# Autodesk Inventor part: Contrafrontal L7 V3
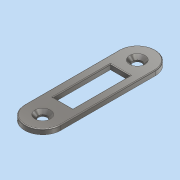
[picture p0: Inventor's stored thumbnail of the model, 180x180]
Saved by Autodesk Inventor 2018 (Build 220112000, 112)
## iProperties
Created: 2020-04
Part Number: Contrafrontal L7 V3
Material: Acero inoxidable
Document SubType Name: Modeling
Designer: PROYECTO
Density: 8 g/cm^3
Appearance: Semipulido
Author: PROYECTO
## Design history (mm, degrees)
sketch "Boceto1"
  geometry: L1 (0, 0)-(0, 80); L2 (11, 11)-(11, 69); L3 (-11, 69)-(-11, 11); L4 (6, 23.5)-(-6, 23.5); L5 (-6, 23.5)-(-6, 58.5); L6 (-6, 58.5)-(6, 58.5); L7 (6, 58.5)-(6, 23.5); L8 (6, 23.5)-(-6, 58.5); L9 (-6, 23.5)-(6, 58.5); C1 r 2.75 at (0, 69); C2 r 2.75 at (0, 11); A1 r 11 centre (0, 11) between (-11, 11) and (11, 11); A2 r 11 centre (0, 69) between (11, 69) and (-11, 69); 2 further points
  constraints: 20 end point, 6 point on circle, 4 centre point, 4 tangent, 3 midpoint, 3 parallel, 3 point on line, 2 coincident, 1 horizontal, 1 perpendicular, 1 vertical
  dimensions: "d0" = 80 distance of L1.start L1.end; "d1" = 22 distance between parallel lines of L2 L3; "d2" = 35 distance of L6.end L4.start; "d3" = 12 distance of L5.end L6.end; "d4" = 1 distance of point (0, 40) point (0, 41); "d5" = 5.5 diameter of C1; "d6" = 5.5 diameter of C2
extrude "Extrusión1" new body sketch "Boceto1" distance "d7" = 3; taper "d8" = 0 deg
fillet "Empalme1" dims "d9" = 0.5
chamfer "Chaflán1" distance "d10" = 2; stored, may be unused: second distance "d11" = 2, angle "d12" = 45 deg
node "Sólido1"
